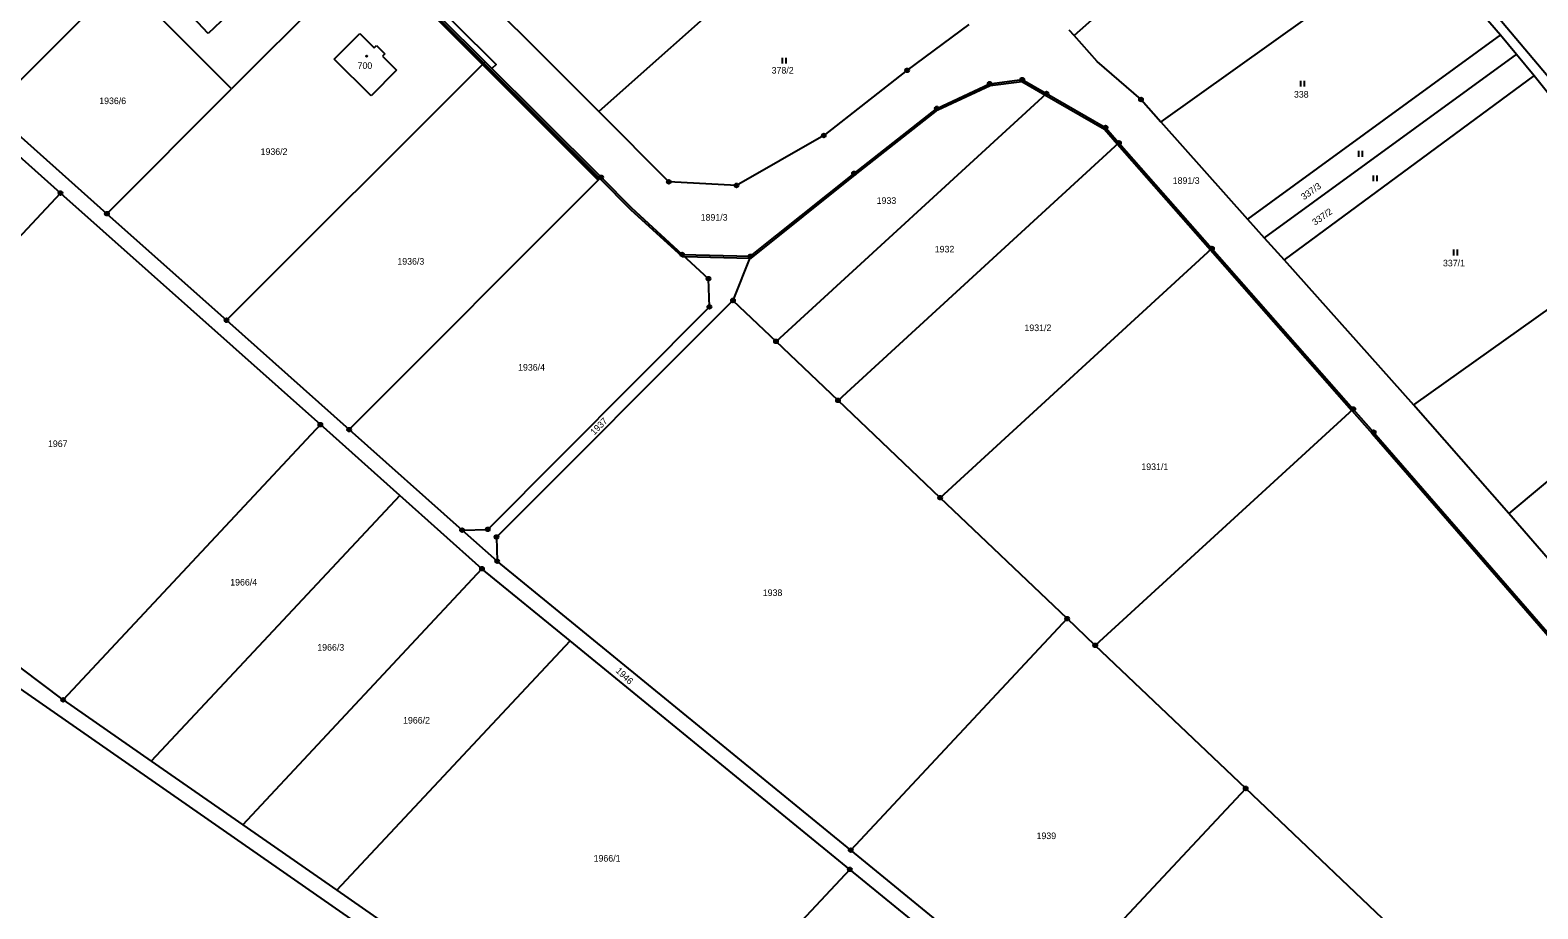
# Model space of a CAD drawing. Extents: x -445050 to -440454, y -1134563 to -1129741.
# Drawn here: x -442582.2 to -442192.6, y -1131427.4 to -1131200.4 of the extents above; entities that cross this region are included whole.
import ezdxf

# ---------------------------------------------------------------- set-up
doc = ezdxf.new("R2010")
doc.units = 0
for name, color, linetype in [('Vrstva 1', 7, 'Continuous'), ('Vrstva 16', 7, 'Continuous'), ('Vrstva 18', 7, 'Continuous'), ('Vrstva 19', 7, 'Continuous'), ('Vrstva 24', 7, 'Continuous'), ('Vrstva 25', 7, 'Continuous'), ('Vrstva 3', 7, 'Continuous'), ('Vrstva 30', 7, 'Continuous'), ('Vrstva 37', 7, 'Continuous'), ('Vrstva 5', 7, 'Continuous'), ('Vrstva 6', 7, 'Continuous')]:
    doc.layers.add(name, color=color, linetype=linetype)

msp = doc.modelspace()

# ---------------------------------------------------------------- linework, layer by layer
at = {"layer": 'Vrstva 1'}
for p, q in [((-442494.57, -1131180.03), (-442530.14, -1131215.59)), ((-442530.14, -1131215.59), (-442556.47, -1131189.23)), ((-442536.19, -1131201.27), (-442540.13, -1131197.05)), ((-442531.25, -1131196.63), (-442536.19, -1131201.27)), ((-442503.65, -1131207.9), (-442497.01, -1131201.22)), ((-442497.01, -1131201.22), (-442493.27, -1131204.98)), ((-442493.27, -1131204.98), (-442492.68, -1131204.38)), ((-442492.68, -1131204.38), (-442490.58, -1131206.48)), ((-442494.11, -1131217.4), (-442503.65, -1131207.9)), ((-442490.58, -1131206.48), (-442491.16, -1131207.1)), ((-442491.16, -1131207.1), (-442487.5, -1131210.77)), ((-442487.5, -1131210.77), (-442494.11, -1131217.4)), ((-442562.36, -1131247.81), (-442530.14, -1131215.59)), ((-442562.36, -1131247.81), (-442592.46, -1131220.99)), ((-442486.7, -1131320.58), (-442507.21, -1131302.31)), ((-442486.7, -1131320.58), (-442550.89, -1131389.24)), ((-442465.44, -1131339.53), (-442486.7, -1131320.58)), ((-442527.27, -1131405.67), (-442465.44, -1131339.53)), ((-442442.66, -1131358.15), (-442465.44, -1131339.53)), ((-442502.92, -1131422.6), (-442442.66, -1131358.15)), ((-442370.38, -1131417.2), (-442442.66, -1131358.15)), ((-442573.67, -1131373.4), (-442550.89, -1131389.24)), ((-442550.89, -1131389.24), (-442527.27, -1131405.67)), ((-442527.27, -1131405.67), (-442502.92, -1131422.6)), ((-442502.92, -1131422.6), (-442425.66, -1131476.33))]:
    msp.add_line(p, q, dxfattribs=at)
for points in [[(-442523.61, -1131152.13), (-442592.46, -1131220.99)], [(-442477.97, -1131178.7), (-442435.23, -1131221.39)], [(-442464.63, -1131208.55), (-442487.64, -1131185.63)], [(-442339.6, -1131198.89), (-442355.56, -1131210.77)], [(-442313.76, -1131200.29), (-442312.38, -1131201.77)], [(-442306.43, -1131208.5), (-442312.38, -1131201.77)], [(-442531.47, -1131275.33), (-442465.33, -1131209.24)], [(-442465.33, -1131209.24), (-442465.04, -1131208.96)], [(-442464.63, -1131208.55), (-442465.04, -1131208.96)], [(-442464.63, -1131208.55), (-442434.66, -1131238.41)], [(-442295.14, -1131218.32), (-442306.43, -1131208.5)], [(-442355.56, -1131210.77), (-442377.1, -1131227.61)], [(-442389.46, -1131280.79), (-442319.56, -1131216.78)], [(-442347.91, -1131220.6), (-442334.26, -1131214.24)], [(-442334.26, -1131214.24), (-442325.82, -1131213.18)], [(-442325.82, -1131213.18), (-442319.56, -1131216.78)], [(-442319.56, -1131216.78), (-442304.29, -1131225.56)], [(-442369.28, -1131237.39), (-442347.91, -1131220.6)], [(-442295.14, -1131218.32), (-442290.03, -1131224.07)], [(-442574.37, -1131242.48), (-442595.68, -1131223.48)], [(-442435.23, -1131221.39), (-442417.16, -1131239.57)], [(-442290.03, -1131224.07), (-442267.61, -1131249.18)], [(-442377.1, -1131227.61), (-442399.67, -1131240.5)], [(-442304.29, -1131225.56), (-442300.83, -1131229.49)], [(-442300.83, -1131229.49), (-442373.44, -1131296.04)], [(-442300.83, -1131229.49), (-442276.8, -1131256.79)], [(-442435.41, -1131239.16), (-442499.75, -1131303.59)], [(-442435.13, -1131238.88), (-442435.41, -1131239.16)], [(-442434.66, -1131238.41), (-442435.13, -1131238.88)], [(-442426.69, -1131246.35), (-442434.66, -1131238.41)], [(-442399.67, -1131240.5), (-442417.16, -1131239.57)], [(-442396.05, -1131258.81), (-442369.28, -1131237.39)], [(-442644.1, -1131317.07), (-442574.37, -1131242.48)], [(-442574.37, -1131242.48), (-442507.21, -1131302.31)], [(-442562.36, -1131247.81), (-442531.47, -1131275.33)], [(-442413.71, -1131258.35), (-442426.69, -1131246.35)], [(-442267.61, -1131249.18), (-442263.27, -1131254.03)], [(-442263.27, -1131254.03), (-442258.17, -1131259.74)], [(-442413.71, -1131258.35), (-442396.05, -1131258.81)], [(-442413.71, -1131258.35), (-442406.9, -1131264.6)], [(-442396.05, -1131258.81), (-442400.58, -1131270.21)], [(-442347.03, -1131321.18), (-442276.8, -1131256.79)], [(-442276.8, -1131256.79), (-442240.29, -1131298.27)], [(-442258.17, -1131259.74), (-442224.73, -1131297.2)], [(-442406.67, -1131271.88), (-442406.9, -1131264.6)], [(-442400.58, -1131270.21), (-442461.7, -1131331.34)], [(-442400.58, -1131270.21), (-442389.46, -1131280.79)], [(-442531.47, -1131275.33), (-442499.75, -1131303.59)], [(-442463.92, -1131329.36), (-442406.67, -1131271.88)], [(-442373.44, -1131296.04), (-442389.46, -1131280.79)], [(-442347.03, -1131321.18), (-442373.44, -1131296.04)], [(-442240.29, -1131298.27), (-442306.96, -1131359.33)], [(-442240.29, -1131298.27), (-442235.02, -1131304.26)], [(-442200.12, -1131325.23), (-442224.73, -1131297.2)], [(-442507.21, -1131302.31), (-442573.67, -1131373.4)], [(-442499.75, -1131303.59), (-442470.58, -1131329.58)], [(-442235.02, -1131304.26), (-442168.28, -1131380.99)], [(-442314.22, -1131352.42), (-442347.03, -1131321.18)], [(-442178.63, -1131350), (-442200.12, -1131325.23)], [(-442470.58, -1131329.58), (-442463.92, -1131329.36)], [(-442461.52, -1131337.57), (-442470.58, -1131329.58)], [(-442461.7, -1131331.34), (-442461.52, -1131337.57)], [(-442370.14, -1131412.24), (-442461.52, -1131337.57)], [(-442314.22, -1131352.42), (-442370.14, -1131412.24)], [(-442306.96, -1131359.33), (-442314.22, -1131352.42)], [(-442573.67, -1131373.4), (-442595.09, -1131357.28)], [(-442428.42, -1131479.28), (-442598.39, -1131361.08)], [(-442268.09, -1131396.29), (-442306.96, -1131359.33)], [(-442320.74, -1131452.6), (-442268.09, -1131396.29)], [(-442179.67, -1131480.38), (-442268.09, -1131396.29)], [(-442320.74, -1131452.6), (-442370.14, -1131412.24)], [(-442370.38, -1131417.2), (-442425.66, -1131476.33)], [(-442323.54, -1131455.47), (-442370.38, -1131417.2)]]:
    msp.add_lwpolyline(points, dxfattribs=at)
at = {"layer": 'Vrstva 24'}
for centre, radius in [((-442355.56, -1131210.77), 0.5), ((-442355.56, -1131210.77), 0.1), ((-442325.82, -1131213.18), 0.5), ((-442325.82, -1131213.18), 0.1), ((-442334.26, -1131214.24), 0.5), ((-442334.26, -1131214.24), 0.1), ((-442319.56, -1131216.78), 0.5), ((-442319.56, -1131216.78), 0.1), ((-442347.91, -1131220.6), 0.5), ((-442347.91, -1131220.6), 0.1), ((-442295.14, -1131218.32), 0.5), ((-442295.14, -1131218.32), 0.1), ((-442377.1, -1131227.61), 0.5), ((-442377.1, -1131227.61), 0.1), ((-442304.29, -1131225.56), 0.5), ((-442304.29, -1131225.56), 0.1), ((-442300.83, -1131229.49), 0.5), ((-442300.83, -1131229.49), 0.1), ((-442434.66, -1131238.41), 0.5), ((-442434.66, -1131238.41), 0.1), ((-442417.16, -1131239.57), 0.5), ((-442417.16, -1131239.57), 0.1), ((-442399.67, -1131240.5), 0.5), ((-442399.67, -1131240.5), 0.1), ((-442369.28, -1131237.39), 0.5), ((-442369.28, -1131237.39), 0.1), ((-442574.37, -1131242.48), 0.5), ((-442574.37, -1131242.48), 0.1), ((-442562.36, -1131247.81), 0.5), ((-442562.36, -1131247.81), 0.1), ((-442413.71, -1131258.35), 0.5), ((-442413.71, -1131258.35), 0.1), ((-442396.05, -1131258.81), 0.5), ((-442396.05, -1131258.81), 0.1), ((-442276.8, -1131256.79), 0.5), ((-442276.8, -1131256.79), 0.1), ((-442406.9, -1131264.6), 0.5), ((-442406.9, -1131264.6), 0.1), ((-442406.67, -1131271.88), 0.5), ((-442400.58, -1131270.21), 0.5), ((-442400.58, -1131270.21), 0.1), ((-442531.47, -1131275.33), 0.5), ((-442531.47, -1131275.33), 0.1), ((-442406.67, -1131271.88), 0.1), ((-442389.46, -1131280.79), 0.5), ((-442389.46, -1131280.79), 0.1), ((-442373.44, -1131296.04), 0.5), ((-442373.44, -1131296.04), 0.1), ((-442240.29, -1131298.27), 0.5), ((-442240.29, -1131298.27), 0.1), ((-442507.21, -1131302.31), 0.5), ((-442507.21, -1131302.31), 0.1), ((-442499.75, -1131303.59), 0.5), ((-442499.75, -1131303.59), 0.1), ((-442235.02, -1131304.26), 0.5), ((-442235.02, -1131304.26), 0.1), ((-442347.03, -1131321.18), 0.5), ((-442347.03, -1131321.18), 0.1), ((-442470.58, -1131329.58), 0.5), ((-442470.58, -1131329.58), 0.1), ((-442463.92, -1131329.36), 0.5), ((-442463.92, -1131329.36), 0.1), ((-442461.7, -1131331.34), 0.5), ((-442461.7, -1131331.34), 0.1), ((-442461.52, -1131337.57), 0.5), ((-442461.52, -1131337.57), 0.1), ((-442465.44, -1131339.53), 0.5), ((-442465.44, -1131339.53), 0.1), ((-442314.22, -1131352.42), 0.5), ((-442314.22, -1131352.42), 0.1), ((-442306.96, -1131359.33), 0.5), ((-442306.96, -1131359.33), 0.1), ((-442573.67, -1131373.4), 0.5), ((-442573.67, -1131373.4), 0.1), ((-442268.09, -1131396.29), 0.5), ((-442268.09, -1131396.29), 0.1), ((-442370.14, -1131412.24), 0.5), ((-442370.14, -1131412.24), 0.1), ((-442370.38, -1131417.2), 0.5), ((-442370.38, -1131417.2), 0.1)]:
    msp.add_circle(centre, radius, dxfattribs=at)
at = {"layer": 'Vrstva 25'}
for p, q in [((-442387.82, -1131209.03), (-442387.82, -1131207.53)), ((-442386.82, -1131209.03), (-442386.82, -1131207.53)), ((-442253.88, -1131214.96), (-442253.88, -1131213.46)), ((-442252.88, -1131214.96), (-442252.88, -1131213.46)), ((-442238.89, -1131233.1), (-442238.89, -1131231.6)), ((-442237.89, -1131233.1), (-442237.89, -1131231.6)), ((-442235.08, -1131239.41), (-442235.08, -1131237.91)), ((-442234.08, -1131239.41), (-442234.08, -1131237.91)), ((-442214.32, -1131258.6), (-442214.32, -1131257.1)), ((-442213.32, -1131258.6), (-442213.32, -1131257.1))]:
    msp.add_line(p, q, dxfattribs=at)
msp.add_circle((-442495.22, -1131207.11), 0.175, dxfattribs=at)
at = {"layer": 'Vrstva 3'}
for points in [[(-442536.19, -1131201.27), (-442540.13, -1131197.05)], [(-442531.25, -1131196.63), (-442536.19, -1131201.27)], [(-442503.65, -1131207.9), (-442497.01, -1131201.22)], [(-442497.01, -1131201.22), (-442493.27, -1131204.98)], [(-442493.27, -1131204.98), (-442492.68, -1131204.38)], [(-442492.68, -1131204.38), (-442490.58, -1131206.48)], [(-442494.11, -1131217.4), (-442503.65, -1131207.9)], [(-442490.58, -1131206.48), (-442491.16, -1131207.1)], [(-442491.16, -1131207.1), (-442487.5, -1131210.77)], [(-442487.5, -1131210.77), (-442494.11, -1131217.4)]]:
    msp.add_lwpolyline(points, dxfattribs=at)
at = {"layer": 'Vrstva 30'}
for points in [[(-442599.27, -1131076.29), (-442591.41, -1131067.23), (-442589.26, -1131069.34), (-442595.69, -1131076.75), (-442527.43, -1131144.09), (-442520.74, -1131136.48), (-442518.48, -1131138.46), (-442525.29, -1131146.2), (-442461.79, -1131209.24), (-442462.86, -1131210.31), (-442464.63, -1131208.55), (-442487.64, -1131185.63), (-442493.86, -1131179.32), (-442520.52, -1131152.26), (-442522.17, -1131150.69), (-442543.02, -1131130.78), (-442563.05, -1131111.66), (-442589.34, -1131085.99), (-442599.27, -1131076.29)], [(-442466.67, -1131207.9), (-442494.57, -1131180.03), (-442494.29, -1131179.75), (-442466.31, -1131207.68), (-442465.04, -1131208.96), (-442465.33, -1131209.24), (-442466.67, -1131207.9)], [(-442435.52, -1131239.05), (-442465.33, -1131209.24), (-442465.04, -1131208.96), (-442435.13, -1131238.88), (-442435.41, -1131239.16), (-442435.52, -1131239.05)]]:
    msp.add_lwpolyline(points, dxfattribs=at)
at = {"layer": 'Vrstva 37'}
msp.add_circle((-442495.22, -1131207.11), 0.175, dxfattribs=at)
at = {"layer": 'Vrstva 5'}
for points in [[(-442488.6, -1131185.37), (-442464.96, -1131208.88)], [(-442464.96, -1131208.88), (-442435.01, -1131238.76)], [(-442347.64, -1131221.02), (-442334.13, -1131214.73)], [(-442334.13, -1131214.73), (-442325.92, -1131213.7)], [(-442325.92, -1131213.7), (-442319.95, -1131217.13)], [(-442319.95, -1131217.13), (-442304.61, -1131225.95)], [(-442368.97, -1131237.78), (-442347.64, -1131221.02)], [(-442304.61, -1131225.95), (-442301.2, -1131229.83)], [(-442301.2, -1131229.83), (-442277.17, -1131257.13)], [(-442435.01, -1131238.76), (-442427.04, -1131246.7)], [(-442395.88, -1131259.31), (-442368.97, -1131237.78)], [(-442427.04, -1131246.7), (-442413.72, -1131258.85)], [(-442413.72, -1131258.85), (-442413.15, -1131258.86)], [(-442413.15, -1131258.86), (-442396.25, -1131259.31)], [(-442396.25, -1131259.31), (-442395.88, -1131259.31)], [(-442277.17, -1131257.13), (-442240.66, -1131298.61)], [(-442240.66, -1131298.61), (-442235.4, -1131304.59)], [(-442235.4, -1131304.59), (-442168.66, -1131381.32)]]:
    msp.add_lwpolyline(points, dxfattribs=at)
at = {"layer": 'Vrstva 6'}
for points in [[(-442223.72, -1131176.73), (-442290.03, -1131224.07)], [(-442223.72, -1131176.73), (-442202.27, -1131201.61)], [(-442214.52, -1131183.09), (-442188.01, -1131214.62)], [(-442397.46, -1131187.78), (-442435.23, -1131221.39)], [(-442296.88, -1131187.98), (-442312.38, -1131201.77)], [(-442202.27, -1131201.61), (-442267.61, -1131249.18)], [(-442202.27, -1131201.61), (-442198.12, -1131206.58)], [(-442198.12, -1131206.58), (-442263.27, -1131254.03)], [(-442198.12, -1131206.58), (-442193.53, -1131212.08)], [(-442193.53, -1131212.08), (-442258.17, -1131259.74)], [(-442193.53, -1131212.08), (-442161.5, -1131252.2)], [(-442161.5, -1131252.2), (-442224.73, -1131297.2)], [(-442141.11, -1131276.04), (-442200.12, -1131325.23)]]:
    msp.add_lwpolyline(points, dxfattribs=at)

# ---------------------------------------------------------------- texts
at = {"layer": 'Vrstva 16'}
for p in [(-442286.95, -1131240.11), (-442408.93, -1131249.6)]:
    msp.add_text('1891/3', height=1.7, dxfattribs=at).set_placement(p)
at = {"layer": 'Vrstva 18'}
for s, p in [('378/2', (-442390.59, -1131211.62)), ('338', (-442255.62, -1131217.82)), ('1936/6', (-442564.35, -1131219.5)), ('1936/2', (-442522.65, -1131232.62)), ('1933', (-442363.45, -1131245.27)), ('1936/3', (-442487.31, -1131260.98)), ('1932', (-442348.44, -1131257.82)), ('337/1', (-442217.11, -1131261.42)), ('1931/2', (-442325.26, -1131278.14)), ('1936/4', (-442456.11, -1131288.35)), ('1967', (-442577.59, -1131308.09)), ('1931/1', (-442295.05, -1131314.04)), ('1966/4', (-442530.5, -1131343.87)), ('1938', (-442392.88, -1131346.58)), ('1966/3', (-442508, -1131360.7)), ('1966/2', (-442485.84, -1131379.53)), ('1939', (-442322.13, -1131409.38)), ('1966/1', (-442436.59, -1131415.19))]:
    msp.add_text(s, height=1.7, dxfattribs=at).set_placement(p)
for s, rotation, p in [('337/3', 35.8578, (-442253.02, -1131244.37)), ('337/2', 35.0181, (-442250.16, -1131250.91)), ('1937', 45, (-442436.42, -1131305.12)), ('1946', 316.188, (-442431.01, -1131366.06))]:
    msp.add_text(s, height=1.7, rotation=rotation, dxfattribs=at).set_placement(p)
at = {"layer": 'Vrstva 19'}
msp.add_text('700', height=1.7, dxfattribs=at).set_placement((-442497.59, -1131210.41))

doc.saveas('drawing.dxf')
